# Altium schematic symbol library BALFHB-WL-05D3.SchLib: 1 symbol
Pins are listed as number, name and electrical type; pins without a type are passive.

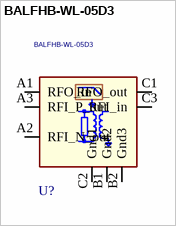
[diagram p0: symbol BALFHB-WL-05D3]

## BALFHB-WL-05D3
designator U?
footprint ST_CSPG8N3x5_213x183x63_nn (Footprint not found)
pins: A1 RFO_in, A2 RFI_N_out, A3 RFI_P_out, B1 Gnd2, B2 Gnd3, C1 RFO_out, C2 Gnd1, C3 RFI_in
